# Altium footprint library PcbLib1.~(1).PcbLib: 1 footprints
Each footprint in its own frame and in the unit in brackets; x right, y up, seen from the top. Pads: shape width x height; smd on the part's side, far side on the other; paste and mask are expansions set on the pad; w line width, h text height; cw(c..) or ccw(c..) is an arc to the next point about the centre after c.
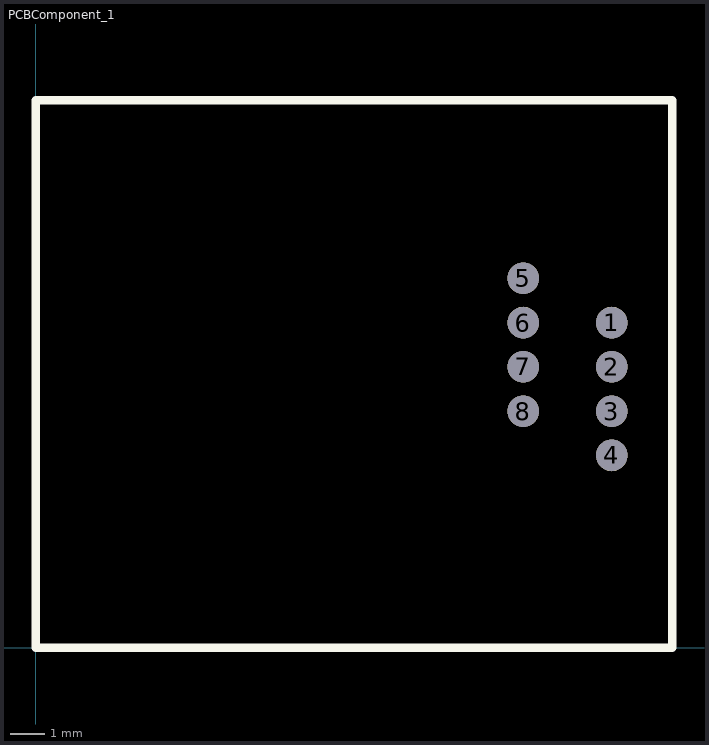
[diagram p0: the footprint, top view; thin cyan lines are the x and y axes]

## PCBComponent_1 [mm]
pads (8):
  round 0.91 hole 0.9: 1(16.515,9.325) 2(16.515,8.055) 3(16.515,6.785) 4(16.515,5.515) 5(13.975,10.595) 6(13.975,9.325) 7(13.975,8.055) 8(13.975,6.785)
Top Overlay:
  lines w0.254: 0,0 0,15.7 18.25,15.7 18.25,0 0,0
